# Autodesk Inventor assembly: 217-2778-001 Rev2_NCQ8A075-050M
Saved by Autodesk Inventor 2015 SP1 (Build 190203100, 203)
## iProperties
Created: 2014-11
Part Number: 217-2778-001 Rev2_NCQ8A075-050M
Document SubType Name: Assembly
Designer: User
Author: User
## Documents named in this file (4)
- C:\Users\User\Documents\6 CIM Gearbox Pack and Go\217-2778-001 Rev2_NCQ8A075-050M.iam
- C:\Users\User\Documents\6 CIM Gearbox Pack and Go\217-2778-NCQ8A075-050M_NCQ8 Tube_075A.ipt
- C:\Users\User\Documents\6 CIM Gearbox Pack and Go\217-2778-NCQ8A075-050M_NCQ8 Rod_075M.ipt
- C:\Users\User\Documents\6 CIM Gearbox Pack and Go\217-2778-NCQ8A075-050M_Snap Ring_075.ipt
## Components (3 placed, 3 different names)
1. 217-2778-NCQ8A075-050M_NCQ8 Tube_075A_101
2. 217-2778-NCQ8A075-050M_NCQ8 Rod_075M_102
3. 217-2778-NCQ8A075-050M_Snap Ring_075_103
